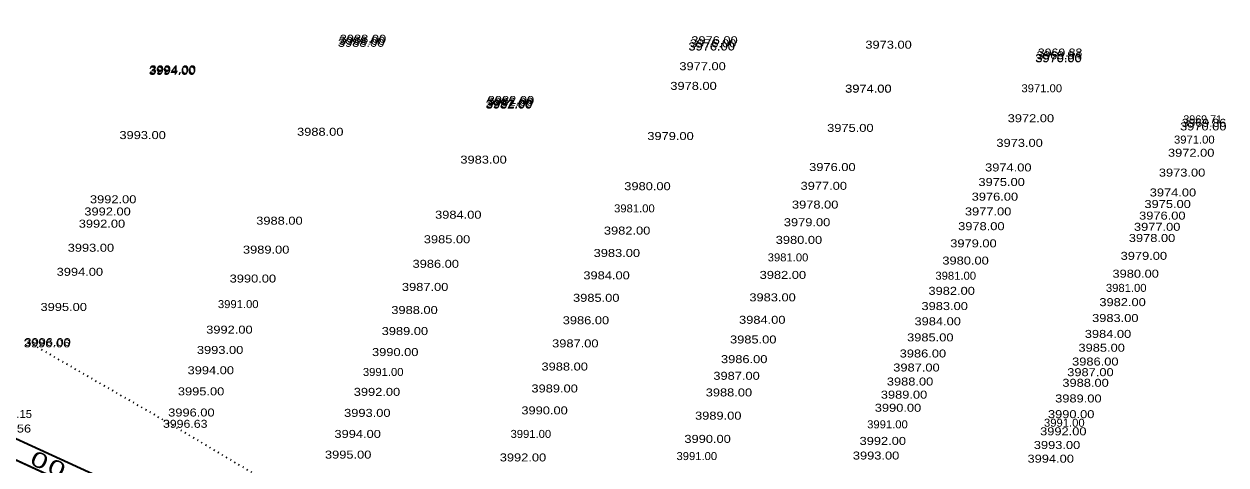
# Model space of a CAD drawing. Extents: x 49942 to 56479, y 47140 to 53283.
# Drawn here: x 50522 to 51273, y 50295 to 50570 of the extents above; entities that cross this region are included whole.
import ezdxf
from ezdxf.enums import TextEntityAlignment as Align

# ---------------------------------------------------------------- set-up
doc = ezdxf.new("R2010")
doc.units = 0
doc.header["$LTSCALE"] = 2
doc.linetypes.add('DOTTED', pattern=[1.5, 0.3, -1.2])
doc.layers.add('29', color=7, linetype='Continuous')
doc.layers.add('59', color=7, linetype='Continuous', lineweight=35)
doc.layers.add('63', color=7, linetype='Continuous', lineweight=35)

msp = doc.modelspace()

# ---------------------------------------------------------------- linework, layer by layer
at = {"layer": '59', "linetype": 'DOTTED'}
for p, q in [((50609.015, 50323.127), (50522.054, 50373.391)), ((50695.507, 50271.844), (50609.015, 50323.127))]:
    msp.add_line(p, q, dxfattribs=at)
at = {"layer": '63'}
for points in [[(51088.959, 50048.79), (49952.321, 50570.45), (49947.316, 50559.544), (51083.954, 50037.883)], [(50910.165, 50104.44), (49942.31, 50548.638), (49947.316, 50559.544), (50915.171, 50115.346)]]:
    msp.add_lwpolyline(points, close=True, dxfattribs=at)

# ---------------------------------------------------------------- texts
at = {"layer": '29'}
for s, width, p in [('3988.00', 1.2, (50718.275, 50556.194)), ('3988.00', 1.2, (50718.866, 50557.48)), ('3988.00', 1.2, (50719.456, 50558.766)), ('3976.00', 1.2, (50938.211, 50555.927)), ('3976.00', 1.2, (50939.082, 50557.825)), ('3976.00', 1.2, (50937.278, 50553.894)), ('3976.00', 1.2, (50937.317, 50553.979)), ('3976.00', 1.2, (50937.34, 50554.03)), ('3973.00', 1.2, (51047.838, 50555.051)), ('3969.94', 1.15, (51154.838, 50548.453)), ('3969.88', 1.15, (51155.612, 50550.14)), ('3977.00', 1.2, (50931.634, 50541.598)), ('3970.00', 1.2, (51153.956, 50546.53)), ('3970.00', 1.2, (51154.026, 50546.684)), ('3970.00', 1.2, (51154.064, 50546.767)), ('3994.00', 1.2, (50600.205, 50538.672)), ('3994.00', 1.2, (50600.422, 50539.145)), ('3994.00', 1.2, (50600.639, 50539.619)), ('3978.00', 1.2, (50925.991, 50529.302)), ('3974.00', 1.2, (51035.197, 50527.508)), ('3974.00', 1.2, (51035.223, 50527.566)), ('3974.00', 1.2, (51035.25, 50527.624)), ('3971.00', 1.05, (51145.36, 50527.801)), ('3982.00', 1.2, (50810.588, 50517.592)), ('3982.00', 1.2, (50810.612, 50517.643)), ('3982.00', 1.2, (50810.635, 50517.695)), ('3982.00', 1.2, (50810.782, 50518.016)), ('3982.00', 1.2, (50810.915, 50518.305)), ('3982.00', 1.2, (50811.418, 50519.4)), ('3982.00', 1.2, (50811.921, 50520.496)), ('3975.00', 1.2, (51023.967, 50503.041)), ('3972.00', 1.2, (51136.764, 50509.071)), ('3970.00', 1.2, (51244.448, 50503.962)), ('3969.86', 1.15, (51245.486, 50506.225)), ('3993.00', 1.2, (50581.793, 50498.555)), ('3988.00', 1.2, (50692.771, 50500.623)), ('3979.00', 1.2, (50911.604, 50497.954)), ('3971.00', 1.05, (51240.676, 50495.742)), ('3973.00', 1.2, (51129.708, 50493.698)), ('3972.00', 1.2, (51236.903, 50487.522)), ('3983.00', 1.2, (50794.814, 50483.223)), ('3976.00', 1.2, (51012.738, 50478.574)), ('3974.00', 1.2, (51122.653, 50478.325)), ('3973.00', 1.2, (51231.206, 50475.11)), ('3980.00', 1.2, (50897.217, 50466.607)), ('3977.00', 1.2, (51007.357, 50466.848)), ('3975.00', 1.2, (51118.479, 50469.232)), ('3992.00', 1.2, (50563.381, 50458.438)), ('3976.00', 1.2, (51114.275, 50460.071)), ('3974.00', 1.2, (51225.51, 50462.699)), ('3992.00', 1.2, (50559.881, 50450.811)), ('3981.00', 1.05, (50890.854, 50452.743)), ('3978.00', 1.2, (51001.975, 50455.122)), ('3977.00', 1.2, (51110.042, 50450.847)), ('3975.00', 1.2, (51222.196, 50455.479)), ('3992.00', 1.2, (50556.381, 50443.185)), ('3988.00', 1.2, (50667.267, 50445.052)), ('3984.00', 1.2, (50779.01, 50448.787)), ('3979.00', 1.2, (50996.915, 50444.097)), ('3976.00', 1.2, (51218.868, 50448.225)), ('3982.00', 1.2, (50884.492, 50438.88)), ('3978.00', 1.2, (51105.809, 50441.623)), ('3977.00', 1.2, (51215.657, 50441.23)), ('3993.00', 1.2, (50549.481, 50428.151)), ('3985.00', 1.2, (50771.972, 50433.452)), ('3980.00', 1.2, (50991.853, 50433.068)), ('3979.00', 1.2, (51100.878, 50430.88)), ('3978.00', 1.2, (51212.447, 50434.236)), ('3989.00', 1.2, (50658.97, 50426.974)), ('3983.00', 1.2, (50878.071, 50424.889)), ('3981.00', 1.05, (50986.829, 50422.12)), ('3980.00', 1.2, (51095.947, 50420.136)), ('3979.00', 1.2, (51207.332, 50423.092)), ('3994.00', 1.2, (50542.581, 50413.117)), ('3986.00', 1.2, (50764.934, 50418.117)), ('3990.00', 1.2, (50650.673, 50408.896)), ('3984.00', 1.2, (50871.649, 50410.897)), ('3982.00', 1.2, (50981.804, 50411.172)), ('3981.00', 1.05, (51091.606, 50410.677)), ('3980.00', 1.2, (51202.218, 50411.947)), ('3987.00', 1.2, (50758.303, 50403.669)), ('3982.00', 1.2, (51087.264, 50401.218)), ('3981.00', 1.05, (51198.143, 50403.068)), ('3995.00', 1.2, (50532.498, 50391.147)), ('3991.00', 1.05, (50643.348, 50392.935)), ('3985.00', 1.2, (50865.209, 50396.865)), ('3983.00', 1.2, (50975.368, 50397.149)), ('3983.00', 1.2, (51082.896, 50391.699)), ('3982.00', 1.2, (51194.049, 50394.15)), ('3988.00', 1.2, (50751.672, 50389.22)), ('3986.00', 1.2, (50858.769, 50382.832)), ('3984.00', 1.2, (50968.932, 50383.125)), ('3983.00', 1.2, (51189.495, 50384.227)), ('3992.00', 1.2, (50636.022, 50376.974)), ('3989.00', 1.2, (50745.644, 50376.086)), ('3984.00', 1.2, (51078.528, 50382.181)), ('3996.06', 1.2, (50522.054, 50368.391)), ('3996.00', 1.2, (50522.415, 50369.177)), ('3987.00', 1.2, (50852.131, 50368.37)), ('3985.00', 1.2, (50963.288, 50370.828)), ('3985.00', 1.2, (51073.911, 50372.122)), ('3984.00', 1.2, (51184.941, 50374.304)), ('3993.00', 1.2, (50630.196, 50364.28)), ('3990.00', 1.2, (50739.616, 50362.952)), ('3986.00', 1.2, (51069.294, 50362.063)), ('3985.00', 1.2, (51180.979, 50365.67)), ('3988.00', 1.2, (50845.494, 50353.908)), ('3986.00', 1.2, (50957.645, 50358.531)), ('3987.00', 1.2, (51065.276, 50353.307)), ('3986.00', 1.2, (51177.016, 50357.036)), ('3994.00', 1.2, (50624.371, 50351.586)), ('3991.00', 1.05, (50733.912, 50350.525)), ('3987.00', 1.2, (50952.87, 50348.129)), ('3987.00', 1.2, (51173.968, 50350.393)), ('3995.00', 1.2, (50618.313, 50338.388)), ('3992.00', 1.2, (50728.209, 50338.099)), ('3989.00', 1.2, (50839.206, 50340.206)), ('3988.00', 1.2, (50948.096, 50337.726)), ('3988.00', 1.2, (51061.258, 50344.552)), ('3988.00', 1.2, (51170.919, 50343.751)), ('3989.00', 1.2, (51057.494, 50336.352)), ('3989.00', 1.2, (51166.427, 50333.964)), ('4004.15', 1.05, (50501.804, 50324.268)), ('3996.00', 1.2, (50612.256, 50325.191)), ('3993.00', 1.2, (50722.174, 50324.949)), ('3990.00', 1.2, (50832.917, 50326.504)), ('3989.00', 1.2, (50941.437, 50323.217)), ('3990.00', 1.2, (51053.731, 50328.152)), ('3990.00', 1.2, (51161.925, 50324.155)), ('4004.56', 1.2, (50497.633, 50315.179)), ('3996.63', 1.15, (50609.015, 50318.127)), ('3991.00', 1.05, (51048.977, 50317.794)), ('3991.00', 1.05, (51159.465, 50318.794)), ('3994.00', 1.2, (50716.139, 50311.799)), ('3991.00', 1.05, (50826.171, 50311.805)), ('3990.00', 1.2, (50934.778, 50308.707)), ('3992.00', 1.2, (51044.223, 50307.436)), ('3992.00', 1.2, (51157.005, 50313.434)), ('3993.00', 1.2, (51153.08, 50304.881)), ('3995.00', 1.2, (50710.207, 50298.875)), ('3992.00', 1.2, (50819.425, 50297.106)), ('3991.00', 1.05, (50929.845, 50297.96)), ('3993.00', 1.2, (51040.026, 50298.291)), ('3994.00', 1.2, (51149.155, 50296.329))]:
    msp.add_text(s, height=5, dxfattribs=dict(at, width=width)).set_placement(p)
msp.add_text('3969.71', height=5, dxfattribs=at).set_placement((51246.498, 50508.428))
at = {"layer": '63', "width": 1.45}
for p in [(50529.86, 50293.506), (50540.623, 50288.566)]:
    msp.add_text('0', height=9.6, rotation=335.347, dxfattribs=at).set_placement(p, align=Align.CENTER)

doc.saveas('drawing.dxf')
